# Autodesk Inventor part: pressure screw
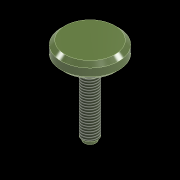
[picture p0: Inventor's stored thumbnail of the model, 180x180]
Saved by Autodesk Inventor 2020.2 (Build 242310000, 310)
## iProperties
Manager: PART
Category: 8
Company: 12
Created: 2020-10
Part Number: pressure screw
Material: Generic
Document SubType Name: Modeling
Designer: Apardo
Density: 1 g/cm^3
Appearance: Dark Olive
Project: PLATE ROLLING MACHINE
Cost Center: 1
Description: PRESSURE SCREW
Engineer: STEEL C45
Vendor: 6
Stock Number: 1.8
Engr Approved By: D. JAEGER
Author: Apardo
Revision Number: 1.0
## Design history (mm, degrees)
sketch "Sketch1"
  geometry: L1 (0, 0)-(0, 102.5); L2 (0, 0)-(3, 0); L3 (3, 0)-(3, 2); L4 (3, 2)-(4, 2); L5 (4, 2)-(4, 37); L6 (4, 37)-(15, 37); L7 (15, 37)-(15, 45); L8 (15, 45)-(0, 45); L9 (0, 0)-(0, 45)
  constraints: 18 end point, 7 perpendicular, 1 horizontal, 1 point on line, 1 vertical
  dimensions: "d0" = 30 diameter of L7 L1; "d1" = 6 diameter of L3 L1; "d2" = 2 distance of L2.end L3.end; "d3" = 8 diameter of L5 L1; "d4" = 8 distance of L6.end L7.end; "d5" = 45 distance between parallel lines of L2 L8
revolve "Revolution1" sketch "Sketch1" stored, may be unused: angle "d6" = 90 deg
chamfer "Chamfer1" distance "d7" = 2; stored, may be unused: second distance "d8" = 2, angle "d9" = 45 deg
fillet "Fillet1" dims "d10" = 2
thread "Thread1" dims "d11" = 32, "d12" = 1
body "Solid1"
